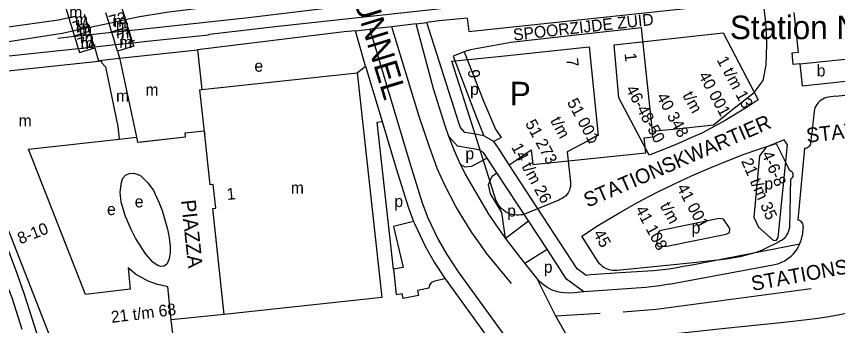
# Model space of a CAD drawing. Extents: x 160673 to 161924, y 382258 to 384145.
# Drawn here: x 161158.4 to 161438.4, y 383598.1 to 383703.4 of the extents above; entities that cross this region are included whole.
import ezdxf

# ---------------------------------------------------------------- set-up
doc = ezdxf.new("R2010")
doc.units = 0
for name, color, linetype in [('BLT_Basislijn', 7, 'Continuous'), ('BLT_Bebouwing', 7, 'Continuous'), ('BLT_Bebouwing_beschrifting', 7, 'Continuous'), ('BLT_Centroide', 7, 'Continuous'), ('BLT_Huisnummer', 7, 'Continuous'), ('BLT_Huisnummer_ tussenligend', 7, 'Continuous'), ('BLT_Huisnummer_reeks', 7, 'Continuous'), ('BLT_Onderdoorgang_en_onderverdeling', 7, 'Continuous'), ('BLT_Onderverdeling_panden', 7, 'Continuous'), ('BLT_Plantopo', 7, 'Continuous'), ('BLT_Spoorlijn', 7, 'Continuous'), ('BLT_Straatnaam', 7, 'Continuous'), ('BLT_Straatnaam_hoofdweg', 7, 'Continuous'), ('BLT_Straatnaam_verkleind', 7, 'Continuous'), ('BLT_Tekst_parkeren', 7, 'Continuous'), ('BLT_Vlakafsluiter', 7, 'Continuous')]:
    doc.layers.add(name, color=color, linetype=linetype)

msp = doc.modelspace()

# ---------------------------------------------------------------- linework, layer by layer
at = {"layer": 'BLT_Basislijn'}
for p, q in [((161312.67, 383698.33), (161398.23, 383707.34)), ((161312.13, 383702.84), (161302.53, 383701.95)), ((161312.13, 383702.84), (161312.67, 383698.33)), ((161286.45, 383699.94), (161278.94, 383699.04)), ((161294.68, 383700.95), (161286.45, 383699.94)), ((161294.68, 383700.95), (161298.31, 383701.41)), ((161297.49, 383690.74), (161294.68, 383700.95)), ((161302.4, 383701.93), (161298.31, 383701.41)), ((161302.53, 383701.95), (161302.4, 383701.93)), ((161274.03, 383698.57), (161278.94, 383699.04)), ((161185.11, 383692.7), (161186.45, 383688.2)), ((161192.86, 383691.62), (161193.6, 383689.19)), ((161300.57, 383678.75), (161297.49, 383690.74)), ((161274.54, 383684.24), (161277.46, 383686.49)), ((161304.63, 383666.1), (161300.57, 383678.75)), ((161437.82, 383676.25), (161465.67, 383679.22)), ((161437.82, 383676.25), (161435.95, 383676)), ((161430.37, 383671.08), (161430.02, 383668.08)), ((161305.9, 383662.47), (161304.63, 383666.1)), ((161430.02, 383668.08), (161429.58, 383663.49)), ((161429.36, 383660.87), (161429.58, 383663.49)), ((161307.8, 383657.64), (161305.9, 383662.47)), ((161429.31, 383660.29), (161429.36, 383660.87)), ((161309.84, 383653.03), (161307.8, 383657.64)), ((161427.11, 383658.59), (161424.89, 383634.02)), ((161311.54, 383649.69), (161309.84, 383653.03)), ((161317.11, 383640.13), (161311.54, 383649.69)), ((161319.44, 383636.06), (161317.11, 383640.13)), ((161322.78, 383631.25), (161319.44, 383636.06)), ((161325.15, 383627.85), (161332.97, 383633.76)), ((161325.15, 383627.85), (161322.78, 383631.25)), ((161426.69, 383631.92), (161426.29, 383628.64)), ((161329.35, 383622.43), (161325.15, 383627.85)), ((161331.8, 383619.31), (161339.32, 383624.08)), ((161387.03, 383618.44), (161425.5, 383625.95)), ((161331.8, 383619.31), (161329.35, 383622.43)), ((161335.84, 383614.19), (161331.8, 383619.31)), ((161380.99, 383612.21), (161416.48, 383618.81)), ((161387.03, 383618.44), (161383.58, 383617.75)), ((161380.82, 383617.3), (161375.61, 383616.77)), ((161383.58, 383617.75), (161380.82, 383617.3)), ((161336.79, 383613.14), (161335.84, 383614.19)), ((161338.12, 383611.96), (161336.79, 383613.14)), ((161339.29, 383611.15), (161338.12, 383611.96)), ((161341.12, 383610.21), (161339.29, 383611.15)), ((161342.86, 383609.62), (161341.12, 383610.21)), ((161372.99, 383611.11), (161351.86, 383609.55)), ((161377.81, 383611.58), (161372.99, 383611.11)), ((161376.49, 383603.71), (161429.39, 383610.76)), ((161380.99, 383612.21), (161377.81, 383611.58)), ((161160.97, 383609.17), (161165.4, 383595.25)), ((161344.01, 383609.35), (161342.86, 383609.62)), ((161345.26, 383609.19), (161344.01, 383609.35)), ((161346.62, 383609.14), (161345.26, 383609.19)), ((161348.55, 383609.29), (161346.62, 383609.14)), ((161351.86, 383609.55), (161348.55, 383609.29)), ((161229.29, 383601.91), (161211.23, 383599.99)), ((161357.49, 383602.16), (161342.36, 383601.29)), ((161365.32, 383602.76), (161376.49, 383603.71))]:
    msp.add_line(p, q, dxfattribs=at)
for points in [[(161409.96, 383677.53), (161413.03, 383681.57), (161414.1, 383686.83), (161414.32, 383693.83), (161414.32, 383693.83), (161414.08, 383699.88), (161413.89, 383701.48), (161413.02, 383708.9)], [(161310.69, 383634.63), (161308.25, 383638.71), (161304.49, 383645.98), (161302.03, 383651.44), (161299.38, 383658.61), (161295.77, 383669.35), (161286.47, 383699.89)], [(161317.77, 383662.79), (161313.62, 383663.5), (161311.32, 383663.9), (161309.77, 383665.64), (161309.21, 383667.15), (161298.31, 383701.41)], [(161375.25, 383664.32), (161371.59, 383699.52), (161327, 383694.6), (161313.25, 383692.01), (161311.05, 383691.35)], [(161270.21, 383698.16), (161220.19, 383692.08)], [(161274.03, 383698.57), (161270.21, 383698.16)], [(161277.46, 383686.49), (161274.03, 383698.57)], [(161278.94, 383699.04), (161292.63, 383653.07), (161296.77, 383639.9), (161298.71, 383634.83), (161302.21, 383627.46), (161305.14, 383622.29), (161309.05, 383616.38), (161345.39, 383566.33)], [(161311.05, 383691.35), (161307.37, 383689.88), (161315.29, 383669.04), (161317.77, 383662.79)], [(161311.05, 383691.35), (161317.79, 383674.38), (161321.77, 383665), (161323.65, 383662.15), (161321.22, 383660.82)], [(161277.46, 383686.49), (161283.09, 383667.59)], [(161160.33, 383596.78), (161156.92, 383607.55), (161144.45, 383639.15), (161128.22, 383682.46)], [(161386.8, 383665.51), (161396.11, 383666.55), (161402.63, 383671.82), (161409.96, 383677.53)], [(161435.95, 383676), (161435.26, 383675.94), (161434.6, 383675.79), (161433.95, 383675.57), (161433.33, 383675.28), (161432.75, 383674.92), (161432.22, 383674.49), (161431.74, 383674), (161431.32, 383673.46), (161430.97, 383672.87), (161430.69, 383672.24), (161430.48, 383671.59), (161430.37, 383671.08)], [(161286.95, 383617.29), (161281.42, 383667.4), (161283.09, 383667.59)], [(161283.09, 383667.59), (161287.85, 383651.61), (161292.05, 383638.26), (161293.82, 383633.61)], [(161326.42, 383652.86), (161328.46, 383654.21), (161333.92, 383657.98), (161334.54, 383652.94), (161373.04, 383656.96), (161372.5, 383662.1), (161375.45, 383662.4), (161375.25, 383664.32)], [(161375.25, 383664.32), (161386.8, 383665.51)], [(161318.94, 383655.15), (161317.68, 383657.08), (161316.05, 383658.01), (161312.77, 383658.58), (161308.75, 383659.27), (161305.9, 383662.47)], [(161321.22, 383660.82), (161317.77, 383662.79)], [(161326.42, 383652.86), (161322.73, 383658.49), (161321.22, 383660.82)], [(161427.11, 383658.59), (161427.52, 383658.59), (161427.91, 383658.67), (161428.28, 383658.83), (161428.61, 383659.06), (161428.9, 383659.35), (161429.11, 383659.68), (161429.26, 383660.06), (161429.31, 383660.29)], [(161318.94, 383655.15), (161313.6, 383652.26), (161311.44, 383652.02), (161309.84, 383653.03)], [(161322.25, 383650.11), (161318.94, 383655.15)], [(161375.61, 383616.77), (161364.23, 383616.02), (161354.17, 383615.33), (161352.68, 383615.17), (161349.66, 383617.43), (161326.42, 383652.86)], [(161144.26, 383651.13), (161151.56, 383634.36), (161158.09, 383617.19), (161160.97, 383609.17)], [(161325.15, 383627.85), (161323.95, 383636.65), (161320.08, 383643.03), (161319.36, 383646.14), (161320.64, 383649.05), (161322.25, 383650.11)], [(161332.97, 383633.76), (161322.25, 383650.11)], [(161293.82, 383633.61), (161287, 383631.88), (161290.26, 383617.89), (161286.95, 383617.29)], [(161293.82, 383633.61), (161294.11, 383632.86), (161297.77, 383625.15), (161300.87, 383619.67), (161304.59, 383614.06)], [(161327.21, 383612.43), (161318.62, 383622.86), (161316.83, 383625.34), (161313.74, 383629.85), (161310.69, 383634.63)], [(161339.32, 383624.08), (161332.97, 383633.76)], [(161426.69, 383631.92), (161426.65, 383632.33), (161426.54, 383632.72), (161426.35, 383633.09), (161426.09, 383633.41), (161425.78, 383633.67), (161425.42, 383633.87), (161425.03, 383633.99), (161424.89, 383634.02)], [(161425.5, 383625.95), (161425.77, 383626.64), (161426.06, 383627.57), (161426.27, 383628.53), (161426.29, 383628.64)], [(161351.86, 383609.55), (161345.96, 383613.95), (161339.32, 383624.08)], [(161416.48, 383618.81), (161417.44, 383619.01), (161418.38, 383619.29), (161419.29, 383619.65), (161420.17, 383620.08), (161421.01, 383620.58), (161421.81, 383621.15), (161422.56, 383621.78), (161423.25, 383622.47), (161423.89, 383623.22), (161424.46, 383624.01), (161424.97, 383624.85), (161425.41, 383625.73), (161425.5, 383625.95)], [(161286.95, 383617.29), (161287.89, 383608.73), (161289.96, 383609)], [(161304.59, 383614.06), (161300.95, 383613.23), (161299.94, 383612.82), (161299.24, 383611.98), (161299.02, 383610.89), (161295.16, 383610.01), (161295.48, 383608.34), (161290.23, 383607.32), (161289.96, 383609)], [(161304.59, 383614.06), (161304.94, 383613.53), (161333.17, 383574.65), (161338.53, 383567.31), (161343.43, 383560.57), (161347.91, 383555.85)], [(161423.16, 383599.57), (161427.03, 383600.01), (161430.88, 383600.52), (161434.73, 383601.12), (161438.56, 383601.79), (161442.37, 383602.55), (161446.17, 383603.38), (161449.95, 383604.29), (161453.71, 383605.27), (161457.45, 383606.34), (161457.8, 383606.44)], [(161383.24, 383595.38), (161400.08, 383597.15), (161419.07, 383599.14), (161423.16, 383599.57)]]:
    msp.add_lwpolyline(points, dxfattribs=at)
for points in [[(161418.18, 383628.07), (161421.33, 383659.66), (161420.15, 383661.43), (161414.05, 383658.9), (161411.75, 383655.96), (161409.79, 383635.06), (161411.38, 383631.64), (161416.43, 383627.22), (161417.48, 383627.1)], [(161197.7, 383630.57), (161195.56, 383635.24), (161194.13, 383640.18), (161193.79, 383643.57), (161194.23, 383646.96), (161194.74, 383648.28), (161195.66, 383649.3), (161196.92, 383649.94), (161198.29, 383650.08), (161199.61, 383649.68), (161200.81, 383649.07), (161203.2, 383646.78), (161205.15, 383644.1), (161206.92, 383640.12), (161208.08, 383637.33), (161209.91, 383630.92), (161210.34, 383628.62), (161210.57, 383627.07), (161210.89, 383625), (161210.86, 383623.04), (161210.47, 383620.96), (161209.79, 383619.13), (161208.74, 383618.33), (161207.64, 383618.23), (161206.59, 383618.56), (161205.08, 383619.61), (161202.5, 383622.39), (161199.04, 383627.84)], [(161377.26, 383629.86), (161376.68, 383625.86), (161377.59, 383624.89), (161380.22, 383625.15), (161400.41, 383629.22), (161401.49, 383629.76), (161401.65, 383631.21), (161399.55, 383634.38), (161398.05, 383634.61), (161377.71, 383630.4)]]:
    msp.add_lwpolyline(points, close=True, dxfattribs=at)
at = {"layer": 'BLT_Bebouwing'}
for p, q in [((161175.06, 383706.95), (161176.28, 383702.97)), ((161194.32, 383706.29), (161195.56, 383702.34)), ((161176.28, 383702.97), (161176.33, 383702.79)), ((161176.33, 383702.79), (161177.65, 383698.49)), ((161183, 383699.64), (161181.64, 383704.13)), ((161190, 383701.14), (161188.93, 383704.7)), ((161195.56, 383702.34), (161196.34, 383699.85)), ((161183.37, 383698.41), (161183, 383699.64)), ((161190.87, 383698.23), (161190, 383701.14)), ((161177.65, 383698.49), (161178.16, 383696.81)), ((161183.72, 383697.25), (161183.37, 383698.41)), ((161184.98, 383693.11), (161183.72, 383697.25)), ((161190.93, 383698.03), (161190.87, 383698.23)), ((161192.18, 383693.87), (161190.93, 383698.03)), ((161192.86, 383691.62), (161192.18, 383693.87)), ((161185.11, 383692.7), (161184.98, 383693.11)), ((161221.66, 383678.51), (161274.54, 383684.24)), ((161193.45, 383661.64), (161199.37, 383662.29)), ((161211.23, 383599.99), (161210.01, 383611.34))]:
    msp.add_line(p, q, dxfattribs=at)
for points in [[(161425.47, 383687.26), (161423.3, 383687.03), (161422.87, 383691.05), (161425.07, 383691.28), (161423.61, 383704.81)], [(161196.34, 383699.85), (161196.71, 383698.66)], [(161178.16, 383696.81), (161178.21, 383696.66)], [(161178.21, 383696.66), (161179.48, 383692.52)], [(161196.71, 383698.66), (161198.02, 383694.49)], [(161198.02, 383694.49), (161198.4, 383693.26), (161192.86, 383691.62)], [(161179.48, 383692.52), (161179.91, 383691.11), (161185.11, 383692.7)], [(161193.6, 383689.19), (161220.19, 383692.08)], [(161220.19, 383692.08), (161221.66, 383678.51)], [(161136.18, 383682.83), (161186.45, 383688.2)], [(161186.45, 383688.2), (161186.56, 383688.21)], [(161186.56, 383688.21), (161186.49, 383688.46), (161193.6, 383689.19)], [(161425.47, 383687.26), (161426.3, 383679.79), (161473.15, 383684.81), (161472.72, 383688.99)], [(161136.18, 383682.83), (161141.5, 383671.49), (161139.81, 383670.82), (161172.83, 383586.55)], [(161274.54, 383684.24), (161282.98, 383607.67)], [(161216.03, 383662.36), (161215.92, 383663.72), (161222.48, 383664.46), (161222.64, 383663.06)], [(161229.29, 383601.91), (161225.37, 383638.01), (161226.36, 383638.12), (161225.5, 383646.12), (161224.51, 383646.01), (161222.64, 383663.06)], [(161210.01, 383611.34), (161209.24, 383611.46), (161206.56, 383612.12), (161203.38, 383613.25), (161199.06, 383615.64), (161196.46, 383617.74), (161197.25, 383610.49), (161181.95, 383608.64), (161162.5, 383658.23), (161193.45, 383661.64)], [(161199.37, 383662.29), (161199.73, 383660.59), (161216.03, 383662.36)], [(161200.17, 383660.64), (161216.03, 383662.36)], [(161282.98, 383607.67), (161229.29, 383601.91)], [(161172.83, 383586.55), (161211.83, 383594.32), (161211.23, 383599.99)]]:
    msp.add_lwpolyline(points, dxfattribs=at)
at = {"layer": 'BLT_Onderdoorgang_en_onderverdeling'}
for points in [[(161186.56, 383688.21), (161187.38, 383688.3), (161187.45, 383687.73), (161188.74, 383686.21), (161193.02, 383665.89), (161193.45, 383661.64)], [(161193.6, 383689.19), (161193.82, 383688.34), (161199.37, 383662.29)], [(161425.47, 383687.26), (161450.99, 383689.95), (161455.21, 383690.43), (161455.58, 383687.17), (161472.72, 383688.99)]]:
    msp.add_lwpolyline(points, dxfattribs=at)
at = {"layer": 'BLT_Onderverdeling_panden'}
for p, q in [((161178.44, 383703.44), (161176.33, 383702.79)), ((161190.87, 383698.23), (161196.34, 383699.85)), ((161178.16, 383696.81), (161183.37, 383698.41))]:
    msp.add_line(p, q, dxfattribs=at)
msp.add_lwpolyline([(161222.64, 383663.06), (161220.97, 383678.44), (161221.66, 383678.51)], dxfattribs=at)
at = {"layer": 'BLT_Plantopo'}
for points in [[(161362.18, 383693.81), (161399.39, 383697.83), (161411.32, 383674.96), (161407.96, 383672.71), (161404.2, 383670.43), (161400.08, 383667.92), (161396.52, 383666.01), (161392.16, 383663.67), (161388.37, 383662.01), (161384.58, 383660.34), (161382.18, 383659.29), (161376.8, 383657.19), (161374.11, 383656.14), (161363.86, 383675.71)], [(161306.83, 383688.16), (161323.83, 383689.93), (161353.64, 383693.08), (161356.81, 383662.86), (161356, 383662.48), (161356.02, 383662.19), (161355.99, 383661.9), (161355.9, 383661.62), (161355.77, 383661.35), (161355.62, 383661.15), (161355.46, 383660.98), (161355.28, 383660.85), (161355.05, 383660.7), (161354.88, 383660.62), (161354.68, 383660.57), (161354.44, 383660.54), (161354.2, 383660.54), (161353.94, 383660.57), (161353.69, 383660.63), (161353.45, 383660.73), (161353.24, 383660.85), (161353.09, 383660.98), (161346.21, 383657.35), (161347.35, 383646.86), (161347.36, 383646), (161347.3, 383645.52), (161347.26, 383645.1), (161347.15, 383644.78), (161346.99, 383644.27), (161346.74, 383643.76), (161346.48, 383643.32), (161346.13, 383642.8), (161345.61, 383642.2), (161344.99, 383641.69), (161344.51, 383641.41), (161343.93, 383641.11), (161343.33, 383640.85), (161331.05, 383635.87), (161330.44, 383635.78), (161329.73, 383635.68), (161328.91, 383635.7), (161327.92, 383635.8), (161327.28, 383635.95), (161326.48, 383636.22), (161325.9, 383636.49), (161325.18, 383636.89), (161324.37, 383637.49), (161323.74, 383638.02), (161323.09, 383638.78), (161322.72, 383639.34), (161322.41, 383639.86), (161322.04, 383640.61), (161314.7, 383663.63)], [(161351.22, 383628.6), (161356.91, 383632.26), (161363.82, 383636.37), (161370, 383639.86), (161376.9, 383643.52), (161382.84, 383646.44), (161388.6, 383649.11), (161395.57, 383652.12), (161401.13, 383654.36), (161406.54, 383656.45), (161411.18, 383658.07), (161417.47, 383660.08), (161418.82, 383657.39), (161420.64, 383653.79), (161421.76, 383651.37), (161421.79, 383651.13), (161422.17, 383651.03), (161422.46, 383650.87), (161422.74, 383650.64), (161422.95, 383650.38), (161423.07, 383650.1), (161423.15, 383649.8), (161423.18, 383649.51), (161423.16, 383649.16), (161423.09, 383648.85), (161422.93, 383648.54), (161422.76, 383648.31), (161422.55, 383648.1), (161422.31, 383647.93), (161422.23, 383643.13), (161422.1, 383635.84), (161422.04, 383632.44), (161421.98, 383631.64), (161421.84, 383631.01), (161421.68, 383630.3), (161421.45, 383629.68), (161421.12, 383629.07), (161420.6, 383628.32), (161420.07, 383627.69), (161419.45, 383627.23), (161418.73, 383626.8), (161418.01, 383626.37), (161414.02, 383624.45), (161412.43, 383623.69), (161410.6, 383623.03), (161405.03, 383621.55), (161400.49, 383620.74), (161389.14, 383619.43), (161371.17, 383617.68), (161363.12, 383616.89), (161362.45, 383616.82), (161361.8, 383616.86), (161361.07, 383616.98), (161360.53, 383617.07), (161359.94, 383617.28), (161359.36, 383617.49), (161358.85, 383617.82), (161358.35, 383618.16), (161357.82, 383618.64), (161357.24, 383619.18), (161356.79, 383619.85), (161354.99, 383622.7)]]:
    msp.add_lwpolyline(points, close=True, dxfattribs=at)
at = {"layer": 'BLT_Spoorlijn'}
for points in [[(161196.71, 383698.66), (161237.54, 383703.08), (161268.6, 383706.85), (161419.72, 383723.35), (161420.47, 383723.43)], [(161362.58, 383714.47), (161340.59, 383710.48), (161330.45, 383709.05), (161247.69, 383700), (161224.1, 383697.23)], [(161195.56, 383702.34), (161200.43, 383703.38), (161210.33, 383704.96), (161237.22, 383708.28)], [(161176.28, 383702.97), (161172.71, 383702.2), (161140.05, 383697.57), (161082.94, 383691.29), (161035.99, 383686.07), (160993.93, 383681.76), (160957.76, 383679.51)], [(161178.44, 383703.44), (161176.28, 383702.97)], [(161190, 383701.14), (161195.56, 383702.34)], [(161177.65, 383698.49), (161183, 383699.64)], [(161183, 383699.64), (161190, 383701.14)], [(160958.31, 383674.84), (160993.55, 383676.62), (161035.91, 383681.22), (161082.7, 383686.23), (161140.28, 383692.48), (161174.01, 383697.7), (161177.65, 383698.49)], [(161172.56, 383696.05), (161178.21, 383696.66)], [(161178.21, 383696.66), (161183.72, 383697.25)], [(161183.72, 383697.25), (161190.93, 383698.03)], [(161190.93, 383698.03), (161196.71, 383698.66)], [(161198.02, 383694.49), (161202.97, 383695.01), (161223.96, 383697.22), (161224.1, 383697.23)], [(161184.98, 383693.11), (161192.18, 383693.87)], [(161192.18, 383693.87), (161198.02, 383694.49)], [(160787.69, 383685.98), (160798.55, 383683.51), (160830.88, 383677.77), (160863.18, 383673.34), (160888.88, 383671.04), (160918.45, 383669.84), (160955.11, 383670.29), (160991.96, 383672.56), (161075.17, 383681.29), (161131.02, 383687.39), (161179.48, 383692.52)], [(161179.48, 383692.52), (161184.98, 383693.11)]]:
    msp.add_lwpolyline(points, dxfattribs=at)
at = {"layer": 'BLT_Vlakafsluiter'}
msp.add_line((161346.52, 383593.96), (161342.36, 383601.29), dxfattribs=at)
msp.add_lwpolyline([(161342.36, 383601.29), (161335.84, 383614.19)], dxfattribs=at)

# ---------------------------------------------------------------- texts
at = {"layer": 'BLT_Bebouwing_beschrifting'}
msp.add_text('Station NS', height=8, dxfattribs=at).set_placement((161401.7, 383695.7))
at = {"layer": 'BLT_Centroide'}
for s, p in [('m', (161176.42, 383702.9)), ('m', (161178.36, 383700.41)), ('m', (161191.54, 383699.85)), ('m', (161179.18, 383697.97)), ('m', (161179.75, 383697.04)), ('m', (161192.35, 383698.49)), ('m', (161180.04, 383694.41)), ('m', (161192.46, 383695.99)), ('m', (161180.3, 383692.34)), ('m', (161193.44, 383692.66)), ('e', (161239.56, 383684.6)), ('b', (161431.28, 383683.01)), ('p', (161313.1, 383676.69)), ('m', (161192.39, 383674.37)), ('m', (161202.41, 383676.48)), ('m', (161159.17, 383665.94)), ('p', (161311.5, 383654.73)), ('m', (161251.97, 383643.06)), ('p', (161413.45, 383644.49)), ('e', (161198.76, 383638.36)), ('p', (161287.28, 383638.48)), ('e', (161189.3, 383635.75)), ('p', (161325.75, 383635.23)), ('p', (161388.62, 383629.48)), ('p', (161338.23, 383616.08))]:
    msp.add_text(s, height=4, dxfattribs=at).set_placement(p)
at = {"layer": 'BLT_Huisnummer'}
for s, rotation, p in [('72', 16.495, (161179.96, 383691.99)), ('71', 16.495, (161193.38, 383693.46)), ('1', 6.1258, (161230.32, 383640.86))]:
    msp.add_text(s, height=4, rotation=rotation, dxfattribs=at).set_placement(p)
at = {"layer": 'BLT_Huisnummer_ tussenligend'}
for s, p in [('73', (161190.67, 383699.67)), ('74', (161178.25, 383697.61))]:
    msp.add_text(s, height=4, rotation=16.495, dxfattribs=at).set_placement(p)
at = {"layer": 'BLT_Huisnummer_reeks'}
for s, rotation, p in [('7', 276.527, (161345.9, 383688.99)), ('1', 276.527, (161365.74, 383690.79)), ('1 t/m 13', 298.4687, (161397.09, 383688.6)), ('9', 276.527, (161312.31, 383685.14)), ('40 001', 298.4687, (161390.84, 383683.35)), ('46-48-50', 298.4687, (161366.06, 383678.7)), ('t/m', 298.4687, (161385.41, 383676.58)), ('51 001', 298.4687, (161346.03, 383674.22)), ('40 348', 298.4687, (161376.55, 383676.13)), ('t/m', 298.4687, (161340.32, 383667.96)), ('51 273', 298.4687, (161331.75, 383666.99)), ('14 t/m 26', 298.4687, (161327.02, 383658.92)), ('21 t/m 35', 293.4687, (161405.45, 383654.15)), ('4-6-8', 293.4687, (161412.43, 383656.57)), ('41 001', 298.4687, (161383.45, 383645.13)), ('41 108', 298.4687, (161369.3, 383637.66)), ('t/m', 298.4687, (161377.74, 383638.87)), ('8-10', 21.432, (161159.72, 383625.73)), ('45', 298.4687, (161355, 383629.51)), ('21 t/m 68', 7.1836, (161190.91, 383598.98))]:
    msp.add_text(s, height=4, rotation=rotation, dxfattribs=at).set_placement(p)
at = {"layer": 'BLT_Straatnaam'}
for s, height, rotation, p in [('STATIONSKWARTIER', 4.9999, 23.4196, (161353.17, 383638.24)), ('STATIONSPLEIN', 4.9999, 6.4196, (161427.99, 383660.39)), ('PIAZZA', 5, 276.1833, (161214.51, 383640.73)), ('STATIONSPLEIN', 4.9999, 10.4196, (161409.44, 383609.87))]:
    msp.add_text(s, height=height, rotation=rotation, dxfattribs=at).set_placement(p)
at = {"layer": 'BLT_Straatnaam_hoofdweg'}
msp.add_text('VESTDIJKTUNNEL', height=8, rotation=286.9892, dxfattribs=at).set_placement((161256.49, 383764.3))
at = {"layer": 'BLT_Straatnaam_verkleind'}
msp.add_text('SPOORZIJDE ZUID', height=4, rotation=6.4196, dxfattribs=at).set_placement((161328.01, 383695.18))
at = {"layer": 'BLT_Tekst_parkeren'}
msp.add_text('P', height=8, dxfattribs=at).set_placement((161326.66, 383673.15))

doc.saveas('drawing.dxf')
